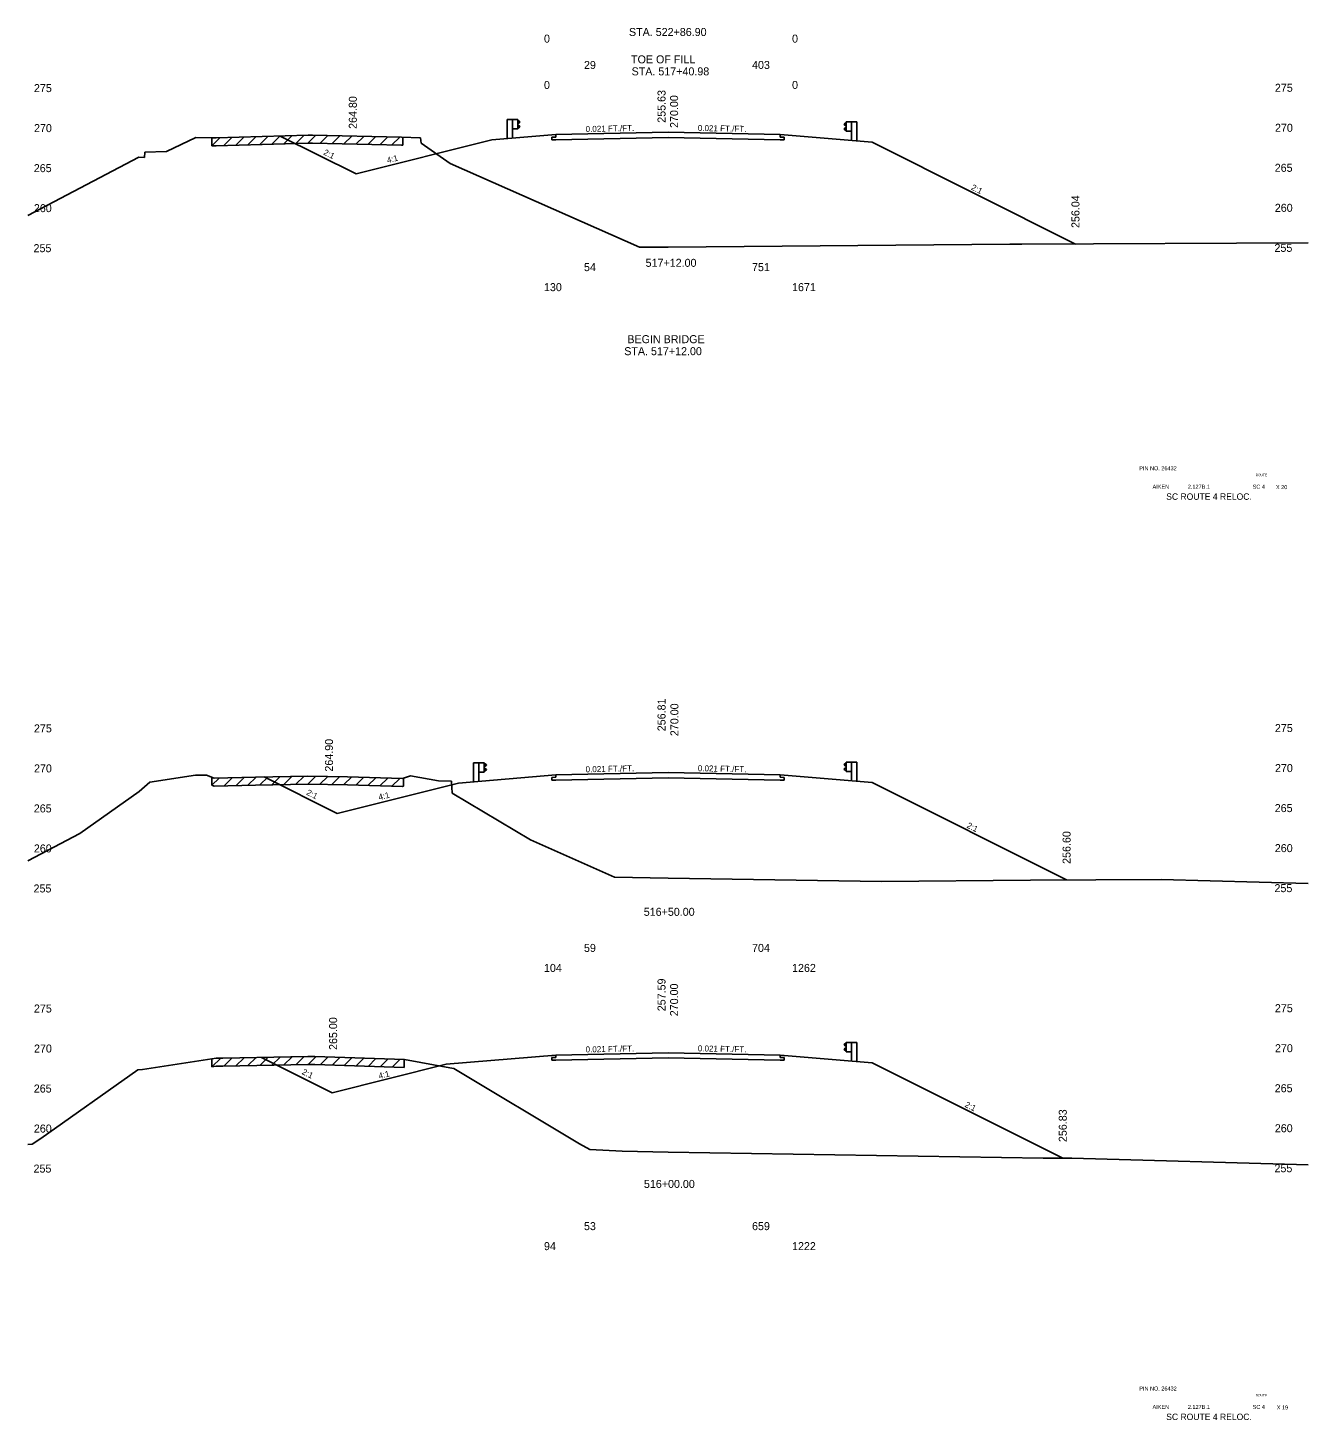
# Model space of a CAD drawing. Extents: x 2967 to 4323, y -3677 to -817.
# Drawn here: x 3188.8 to 3348.8, y -1510.8 to -1336.8 of the extents above; entities that cross this region are included whole.
import ezdxf

# ---------------------------------------------------------------- set-up
doc = ezdxf.new("R2010")
doc.units = 0
for name, color, linetype in [('Level 1', 7, 'Continuous'), ('Level 10', 7, 'Continuous'), ('Level 11', 7, 'Continuous'), ('Level 12', 7, 'Continuous'), ('Level 20', 7, 'Continuous'), ('Level 24', 7, 'Continuous'), ('Level 3', 7, 'Continuous'), ('Level 32', 7, 'Continuous'), ('Level 33', 7, 'Continuous'), ('Level 59', 7, 'Continuous'), ('Level 6', 7, 'Continuous'), ('Level 60', 7, 'Continuous'), ('Level 61', 7, 'Continuous'), ('Level 7', 7, 'Continuous')]:
    doc.layers.add(name, color=color, linetype=linetype)

msp = doc.modelspace()

# ---------------------------------------------------------------- linework, layer by layer
at = {"layer": 'Level 11'}
for p, q in [((3254.76, -1350.43), (3254.26, -1350.44)), ((3254.76, -1350.43), (3254.26, -1350.44)), ((3254.76, -1350.43), (3254.26, -1350.44)), ((3254.26, -1350.44), (3254.26, -1350.78)), ((3254.26, -1350.44), (3254.26, -1350.78)), ((3254.26, -1350.44), (3254.26, -1350.78)), ((3254.26, -1350.78), (3254.76, -1350.77)), ((3254.26, -1350.78), (3254.76, -1350.77)), ((3254.26, -1350.78), (3254.76, -1350.77)), ((3254.76, -1350.13), (3254.76, -1350.43)), ((3254.76, -1350.13), (3254.76, -1350.43)), ((3254.76, -1350.13), (3254.76, -1350.43)), ((3282.76, -1350.43), (3282.76, -1350.13)), ((3282.76, -1350.43), (3282.76, -1350.13)), ((3283.26, -1350.44), (3282.76, -1350.43)), ((3283.26, -1350.44), (3282.76, -1350.43)), ((3282.76, -1350.77), (3283.26, -1350.78)), ((3282.76, -1350.77), (3283.26, -1350.78)), ((3283.26, -1350.78), (3283.26, -1350.44)), ((3283.26, -1350.78), (3283.26, -1350.44)), ((3254.76, -1430.43), (3254.26, -1430.44)), ((3254.26, -1430.44), (3254.26, -1430.78)), ((3254.26, -1430.78), (3254.76, -1430.77)), ((3254.76, -1430.13), (3254.76, -1430.43)), ((3282.76, -1430.43), (3282.76, -1430.13)), ((3283.26, -1430.44), (3282.76, -1430.43)), ((3282.76, -1430.77), (3283.26, -1430.78)), ((3283.26, -1430.78), (3283.26, -1430.44)), ((3254.76, -1465.43), (3254.26, -1465.44)), ((3254.26, -1465.44), (3254.26, -1465.78)), ((3254.26, -1465.78), (3254.76, -1465.77)), ((3254.76, -1465.13), (3254.76, -1465.43)), ((3282.76, -1465.43), (3282.76, -1465.13)), ((3283.26, -1465.44), (3282.76, -1465.43)), ((3282.76, -1465.77), (3283.26, -1465.78)), ((3283.26, -1465.78), (3283.26, -1465.44))]:
    msp.add_line(p, q, dxfattribs=at)
at = {"layer": 'Level 12'}
for p, q in [((3254.76, -1350.13), (3268.76, -1349.84)), ((3268.76, -1349.84), (3282.76, -1350.13)), ((3268.76, -1349.84), (3282.76, -1350.13)), ((3268.76, -1349.84), (3282.76, -1350.13)), ((3291.03, -1348.62), (3290.76, -1348.82)), ((3290.76, -1348.82), (3290.76, -1348.87)), ((3290.76, -1348.87), (3291.03, -1349.07)), ((3290.76, -1349.39), (3291.03, -1349.19)), ((3290.76, -1349.44), (3290.76, -1349.39)), ((3291.03, -1349.64), (3290.76, -1349.44)), ((3291.03, -1349.72), (3291.03, -1348.55)), ((3291.03, -1348.55), (3291.7, -1348.55)), ((3291.03, -1349.72), (3291.7, -1349.72)), ((3291.7, -1348.55), (3291.7, -1350.88)), ((3291.7, -1348.55), (3292.36, -1348.55)), ((3292.36, -1348.55), (3292.36, -1350.93)), ((3268.76, -1350.48), (3254.76, -1350.77)), ((3282.76, -1350.77), (3268.76, -1350.48)), ((3282.76, -1350.77), (3268.76, -1350.48)), ((3282.76, -1350.77), (3268.76, -1350.48)), ((3282.76, -1350.13), (3290.76, -1350.8)), ((3282.76, -1350.43), (3282.76, -1350.13)), ((3283.26, -1350.44), (3282.76, -1350.43)), ((3282.76, -1350.77), (3283.26, -1350.78)), ((3283.26, -1350.78), (3283.26, -1350.44)), ((3290.76, -1350.8), (3294.26, -1351.09)), ((3294.26, -1351.09), (3319.68, -1363.8)), ((3245.12, -1428.61), (3244.46, -1428.61)), ((3244.46, -1428.61), (3244.46, -1430.99)), ((3245.79, -1428.61), (3245.12, -1428.61)), ((3245.12, -1428.61), (3245.12, -1430.94)), ((3245.79, -1429.77), (3245.12, -1429.77)), ((3245.79, -1429.77), (3245.79, -1428.61)), ((3245.79, -1428.68), (3246.06, -1428.88)), ((3246.06, -1428.93), (3245.79, -1429.13)), ((3246.06, -1429.45), (3245.79, -1429.25)), ((3245.79, -1429.7), (3246.06, -1429.5)), ((3246.06, -1428.88), (3246.06, -1428.93)), ((3246.06, -1429.5), (3246.06, -1429.45)), ((3268.76, -1430.48), (3254.76, -1430.77)), ((3282.76, -1430.77), (3268.76, -1430.48)), ((3268.76, -1465.48), (3254.76, -1465.77)), ((3282.76, -1465.77), (3268.76, -1465.48))]:
    msp.add_line(p, q, dxfattribs=at)
at = {"layer": 'Level 24'}
for p, q in [((3248.66, -1348.26), (3248.66, -1350.64)), ((3248.66, -1348.26), (3249.32, -1348.26)), ((3249.99, -1348.26), (3249.32, -1348.26)), ((3249.32, -1348.26), (3249.32, -1350.59)), ((3249.99, -1349.42), (3249.32, -1349.42)), ((3249.99, -1349.42), (3249.99, -1348.26)), ((3249.99, -1348.33), (3250.26, -1348.53)), ((3250.26, -1348.58), (3249.99, -1348.78)), ((3250.26, -1349.1), (3249.99, -1348.9)), ((3249.99, -1349.35), (3250.26, -1349.15)), ((3250.26, -1348.53), (3250.26, -1348.58)), ((3250.26, -1349.15), (3250.26, -1349.1)), ((3291.03, -1348.62), (3290.76, -1348.82)), ((3291.03, -1348.62), (3290.76, -1348.82)), ((3290.76, -1348.82), (3290.76, -1348.87)), ((3290.76, -1348.82), (3290.76, -1348.87)), ((3290.76, -1348.87), (3291.03, -1349.07)), ((3290.76, -1348.87), (3291.03, -1349.07)), ((3290.76, -1349.39), (3291.03, -1349.19)), ((3290.76, -1349.39), (3291.03, -1349.19)), ((3290.76, -1349.44), (3290.76, -1349.39)), ((3290.76, -1349.44), (3290.76, -1349.39)), ((3291.03, -1349.64), (3290.76, -1349.44)), ((3291.03, -1349.64), (3290.76, -1349.44)), ((3291.03, -1349.72), (3291.03, -1348.55)), ((3291.03, -1348.55), (3291.7, -1348.55)), ((3291.03, -1349.72), (3291.03, -1348.55)), ((3291.03, -1348.55), (3291.7, -1348.55)), ((3291.03, -1349.72), (3291.7, -1349.72)), ((3291.03, -1349.72), (3291.7, -1349.72)), ((3291.7, -1348.55), (3291.7, -1350.88)), ((3291.7, -1348.55), (3292.36, -1348.55)), ((3291.7, -1348.55), (3291.7, -1350.88)), ((3291.7, -1348.55), (3292.36, -1348.55)), ((3292.36, -1348.55), (3292.36, -1350.93)), ((3292.36, -1348.55), (3292.36, -1350.93)), ((3245.12, -1428.61), (3244.46, -1428.61)), ((3244.46, -1428.61), (3244.46, -1430.99)), ((3245.12, -1428.61), (3244.46, -1428.61)), ((3244.46, -1428.61), (3244.46, -1430.99)), ((3245.79, -1428.61), (3245.12, -1428.61)), ((3245.12, -1428.61), (3245.12, -1430.94)), ((3245.79, -1428.61), (3245.12, -1428.61)), ((3245.12, -1428.61), (3245.12, -1430.94)), ((3245.79, -1429.77), (3245.12, -1429.77)), ((3245.79, -1429.77), (3245.12, -1429.77)), ((3245.79, -1429.77), (3245.79, -1428.61)), ((3245.79, -1429.77), (3245.79, -1428.61)), ((3245.79, -1428.68), (3246.06, -1428.88)), ((3245.79, -1428.68), (3246.06, -1428.88)), ((3246.06, -1428.93), (3245.79, -1429.13)), ((3246.06, -1428.93), (3245.79, -1429.13)), ((3246.06, -1429.45), (3245.79, -1429.25)), ((3246.06, -1429.45), (3245.79, -1429.25)), ((3245.79, -1429.7), (3246.06, -1429.5)), ((3245.79, -1429.7), (3246.06, -1429.5)), ((3246.06, -1428.88), (3246.06, -1428.93)), ((3246.06, -1428.88), (3246.06, -1428.93)), ((3246.06, -1429.5), (3246.06, -1429.45)), ((3246.06, -1429.5), (3246.06, -1429.45)), ((3291.03, -1428.62), (3290.76, -1428.82)), ((3290.76, -1428.82), (3290.76, -1428.87)), ((3290.76, -1428.87), (3291.03, -1429.07)), ((3290.76, -1429.39), (3291.03, -1429.19)), ((3290.76, -1429.44), (3290.76, -1429.39)), ((3291.03, -1429.64), (3290.76, -1429.44)), ((3291.03, -1429.72), (3291.03, -1428.55)), ((3291.03, -1428.55), (3291.7, -1428.55)), ((3291.03, -1429.72), (3291.7, -1429.72)), ((3291.7, -1428.55), (3291.7, -1430.88)), ((3291.7, -1428.55), (3292.36, -1428.55)), ((3292.36, -1428.55), (3292.36, -1430.93)), ((3291.03, -1463.62), (3290.76, -1463.82)), ((3290.76, -1463.82), (3290.76, -1463.87)), ((3290.76, -1463.87), (3291.03, -1464.07)), ((3290.76, -1464.39), (3291.03, -1464.19)), ((3290.76, -1464.44), (3290.76, -1464.39)), ((3291.03, -1464.64), (3290.76, -1464.44)), ((3291.03, -1464.72), (3291.03, -1463.55)), ((3291.03, -1463.55), (3291.7, -1463.55)), ((3291.03, -1464.72), (3291.7, -1464.72)), ((3291.7, -1463.55), (3291.7, -1465.88)), ((3291.7, -1463.55), (3292.36, -1463.55)), ((3292.36, -1463.55), (3292.36, -1465.93))]:
    msp.add_line(p, q, dxfattribs=at)
at = {"layer": 'Level 59'}
for p, q in [((3254.76, -1350.13), (3268.76, -1349.84)), ((3254.76, -1350.13), (3268.76, -1349.84)), ((3268.76, -1349.84), (3282.76, -1350.13)), ((3268.76, -1349.84), (3282.76, -1350.13)), ((3254.76, -1430.13), (3268.76, -1429.84)), ((3268.76, -1429.84), (3282.76, -1430.13)), ((3254.76, -1465.13), (3268.76, -1464.84)), ((3268.76, -1464.84), (3282.76, -1465.13))]:
    msp.add_line(p, q, dxfattribs=at)
at = {"layer": 'Level 6'}
for p, q in [((3246.76, -1350.8), (3254.76, -1350.13)), ((3282.76, -1350.13), (3290.76, -1350.8)), ((3282.76, -1350.13), (3290.76, -1350.8)), ((3290.76, -1350.8), (3294.26, -1351.09)), ((3290.76, -1350.8), (3294.26, -1351.09)), ((3242.56, -1431.15), (3254.76, -1430.13)), ((3282.76, -1430.13), (3290.76, -1430.8)), ((3290.76, -1430.8), (3294.26, -1431.09)), ((3241.03, -1466.28), (3254.76, -1465.13)), ((3282.76, -1465.13), (3290.76, -1465.8)), ((3290.76, -1465.8), (3294.26, -1466.09))]:
    msp.add_line(p, q, dxfattribs=at)
at = {"layer": 'Level 60'}
for p, q in [((3206.1, -1352.23), (3209.77, -1350.51)), ((3209.77, -1350.51), (3211.71, -1350.55)), ((3211.71, -1350.55), (3212.28, -1350.53)), ((3212.28, -1350.53), (3223.78, -1350.21)), ((3223.78, -1350.21), (3224.33, -1350.22)), ((3224.33, -1350.22), (3235.45, -1350.44)), ((3235.45, -1350.44), (3237.81, -1350.53)), ((3237.81, -1350.53), (3237.93, -1351.2)), ((3237.93, -1351.2), (3241.52, -1353.73)), ((3188.76, -1360.23), (3202.64, -1352.97)), ((3202.64, -1352.97), (3203.34, -1352.99)), ((3203.34, -1352.99), (3203.38, -1352.31)), ((3203.38, -1352.31), (3206.1, -1352.23)), ((3241.52, -1353.73), (3265.19, -1364.18)), ((3268.76, -1364.21), (3311.49, -1363.82)), ((3311.49, -1363.82), (3312.96, -1363.84)), ((3312.96, -1363.84), (3348.76, -1363.65)), ((3265.19, -1364.18), (3268.76, -1364.21)), ((3202.69, -1432.21), (3204.01, -1431.02)), ((3204.01, -1431.02), (3209.7, -1430.18)), ((3209.7, -1430.18), (3211.07, -1430.16)), ((3211.07, -1430.16), (3212.05, -1430.55)), ((3212.05, -1430.55), (3217.2, -1430.41)), ((3217.2, -1430.41), (3223.76, -1430.27)), ((3223.76, -1430.27), (3228.71, -1430.36)), ((3228.71, -1430.36), (3235.6, -1430.59)), ((3235.6, -1430.59), (3236.58, -1430.25)), ((3236.58, -1430.25), (3240.08, -1430.88)), ((3240.08, -1430.88), (3241.7, -1430.9)), ((3241.7, -1430.9), (3241.79, -1432.4)), ((3195.26, -1437.47), (3202.69, -1432.21)), ((3241.79, -1432.4), (3251.56, -1438.26)), ((3188.76, -1440.85), (3195.26, -1437.47)), ((3251.56, -1438.26), (3262.09, -1442.93)), ((3262.09, -1442.93), (3268.76, -1443.03)), ((3268.76, -1443.03), (3295.42, -1443.44)), ((3295.42, -1443.44), (3314.05, -1443.27)), ((3314.05, -1443.27), (3330.38, -1443.19)), ((3330.38, -1443.19), (3348.76, -1443.72)), ((3203.07, -1466.92), (3212.29, -1465.54)), ((3212.29, -1465.54), (3213.13, -1465.53)), ((3213.13, -1465.53), (3223.75, -1465.31)), ((3223.75, -1465.31), (3224.61, -1465.33)), ((3224.61, -1465.33), (3235.81, -1465.7)), ((3235.81, -1465.7), (3241.5, -1466.72)), ((3190.4, -1475.55), (3202.5, -1466.99)), ((3202.5, -1466.99), (3203.07, -1466.92)), ((3241.5, -1466.72), (3242.01, -1466.81)), ((3242.01, -1466.81), (3257.69, -1476.22)), ((3188.76, -1476.3), (3189.29, -1476.25)), ((3189.29, -1476.25), (3190.4, -1475.55)), ((3257.69, -1476.22), (3259.01, -1476.92)), ((3259.01, -1476.92), (3263.03, -1477.16)), ((3263.03, -1477.16), (3268.76, -1477.25)), ((3268.76, -1477.25), (3315.63, -1478)), ((3315.63, -1478), (3319.24, -1478.01)), ((3319.24, -1478.01), (3348.76, -1478.87))]:
    msp.add_line(p, q, dxfattribs=at)
at = {"layer": 'Level 61'}
for p, q in [((3212.77, -1350.52), (3211.74, -1351.55)), ((3211.74, -1350.55), (3211.74, -1351.55)), ((3211.74, -1351.55), (3212.28, -1351.53)), ((3212.28, -1351.53), (3223.78, -1351.21)), ((3214.27, -1350.48), (3213.24, -1351.51)), ((3215.77, -1350.44), (3214.74, -1351.46)), ((3217.27, -1350.39), (3216.24, -1351.42)), ((3218.77, -1350.35), (3217.74, -1351.38)), ((3220.27, -1350.31), (3219.24, -1351.34)), ((3221.77, -1350.27), (3220.74, -1351.29)), ((3223.27, -1350.22), (3222.24, -1351.25)), ((3224.72, -1350.23), (3223.74, -1351.21)), ((3223.78, -1351.21), (3224.33, -1351.22)), ((3224.33, -1351.22), (3235.45, -1351.44)), ((3226.23, -1350.26), (3225.24, -1351.24)), ((3227.73, -1350.29), (3226.74, -1351.27)), ((3229.23, -1350.32), (3228.24, -1351.3)), ((3230.73, -1350.35), (3229.74, -1351.33)), ((3232.23, -1350.38), (3231.24, -1351.36)), ((3233.73, -1350.4), (3232.74, -1351.39)), ((3235.23, -1350.43), (3234.24, -1351.41)), ((3235.45, -1351.44), (3235.61, -1351.44)), ((3235.61, -1351.44), (3235.61, -1350.44)), ((3211.76, -1430.43), (3211.76, -1431.43)), ((3212.66, -1430.53), (3211.76, -1431.43)), ((3211.76, -1431.43), (3212.05, -1431.55)), ((3212.05, -1431.55), (3217.2, -1431.41)), ((3214.29, -1430.49), (3213.26, -1431.52)), ((3215.79, -1430.45), (3214.76, -1431.48)), ((3217.29, -1430.4), (3216.26, -1431.43)), ((3217.2, -1431.41), (3223.76, -1431.27)), ((3218.78, -1430.37), (3217.76, -1431.39)), ((3220.28, -1430.34), (3219.26, -1431.36)), ((3221.78, -1430.31), (3220.76, -1431.33)), ((3223.28, -1430.28), (3222.26, -1431.3)), ((3224.74, -1430.29), (3223.76, -1431.27)), ((3223.76, -1431.27), (3228.71, -1431.36)), ((3226.24, -1430.32), (3225.26, -1431.3)), ((3227.74, -1430.34), (3226.76, -1431.33)), ((3229.23, -1430.38), (3228.26, -1431.35)), ((3228.71, -1431.36), (3235.6, -1431.59)), ((3230.73, -1430.43), (3229.76, -1431.4)), ((3232.23, -1430.48), (3231.26, -1431.45)), ((3233.73, -1430.53), (3232.76, -1431.5)), ((3235.23, -1430.58), (3234.26, -1431.55)), ((3235.6, -1431.59), (3235.7, -1431.56)), ((3235.7, -1431.56), (3235.7, -1430.56)), ((3212.86, -1465.53), (3211.77, -1466.62)), ((3211.77, -1465.62), (3211.77, -1466.62)), ((3213.13, -1466.53), (3223.75, -1466.31)), ((3214.29, -1465.5), (3213.27, -1466.52)), ((3215.79, -1465.47), (3214.77, -1466.49)), ((3217.29, -1465.44), (3216.27, -1466.46)), ((3218.79, -1465.41), (3217.77, -1466.43)), ((3220.29, -1465.38), (3219.27, -1466.4)), ((3221.79, -1465.35), (3220.77, -1466.37)), ((3223.29, -1465.31), (3222.27, -1466.34)), ((3223.75, -1466.31), (3224.61, -1466.33)), ((3224.74, -1465.34), (3223.77, -1466.31)), ((3224.61, -1466.33), (3235.78, -1466.7)), ((3226.24, -1465.39), (3225.27, -1466.35)), ((3227.74, -1465.44), (3226.77, -1466.4)), ((3229.24, -1465.49), (3228.27, -1466.45)), ((3230.74, -1465.54), (3229.77, -1466.5)), ((3232.24, -1465.58), (3231.27, -1466.55)), ((3233.74, -1465.63), (3232.77, -1466.6)), ((3235.24, -1465.68), (3234.27, -1466.65)), ((3235.78, -1466.7), (3235.78, -1465.7)), ((3211.77, -1466.62), (3212.29, -1466.54)), ((3212.29, -1466.54), (3213.13, -1466.53))]:
    msp.add_line(p, q, dxfattribs=at)
at = {"layer": 'Level 7'}
for p, q in [((3220.29, -1350.31), (3229.77, -1355.05)), ((3246.76, -1350.8), (3229.77, -1355.05)), ((3294.26, -1351.09), (3319.68, -1363.8)), ((3294.26, -1351.09), (3319.68, -1363.8)), ((3218.3, -1430.38), (3227.41, -1434.94)), ((3242.56, -1431.15), (3227.41, -1434.94)), ((3294.26, -1431.09), (3318.57, -1443.25)), ((3217.96, -1465.43), (3226.78, -1469.84)), ((3241.03, -1466.28), (3226.78, -1469.84)), ((3294.26, -1466.09), (3318.09, -1478.01))]:
    msp.add_line(p, q, dxfattribs=at)

# ---------------------------------------------------------------- texts
at = {"layer": 'Level 1'}
for s, p in [('0', (3253.26, -1338.64)), ('0', (3284.26, -1338.64)), ('29', (3258.26, -1341.93)), ('403', (3279.26, -1341.93)), ('0', (3253.26, -1344.43)), ('0', (3284.26, -1344.43)), ('54', (3258.26, -1367.19)), ('751', (3279.26, -1367.19)), ('130', (3253.26, -1369.69)), ('1671', (3284.26, -1369.69)), ('BEGIN BRIDGE', (3263.68, -1376.19)), ('STA. 517+12.00', (3263.29, -1377.69)), ('59', (3258.26, -1452.25)), ('704', (3279.26, -1452.25)), ('104', (3253.26, -1454.75)), ('1262', (3284.26, -1454.75)), ('53', (3258.26, -1487.01)), ('659', (3279.26, -1487.01)), ('94', (3253.26, -1489.51)), ('1222', (3284.26, -1489.51))]:
    msp.add_text(s, height=1, dxfattribs=at).set_placement(p)
at = {"layer": 'Level 10'}
for s, p in [('STA. 522+86.90', (3263.88, -1337.81)), ('TOE OF FILL', (3264.14, -1341.23)), ('STA. 517+40.98', (3264.21, -1342.73)), ('517+12.00', (3265.96, -1366.65)), ('516+50.00', (3265.73, -1447.74)), ('516+00.00', (3265.75, -1481.74))]:
    msp.add_text(s, height=1, dxfattribs=at).set_placement(p)
for s, p in [('255.63', (3268.45, -1348.65)), ('256.81', (3268.45, -1424.68)), ('257.59', (3268.45, -1459.66))]:
    msp.add_text(s, height=1, rotation=90, dxfattribs=at).set_placement(p)
at = {"layer": 'Level 20'}
for s, height, p in [('PIN NO. 26432', 0.5, (3327.65, -1392.07)), ('ROUTE', 0.3, (3342.19, -1392.81)), ('AIKEN', 0.5, (3329.31, -1394.37)), ('SC ROUTE 4 RELOC.', 0.8, (3331.02, -1395.76)), (' 2.127B.1', 0.5, (3333.53, -1394.37)), ('SC 4', 0.5, (3341.82, -1394.37)), ('X 20', 0.5, (3344.73, -1394.43)), ('PIN NO. 26432', 0.5, (3327.65, -1507.05)), ('ROUTE', 0.3, (3342.19, -1507.79)), ('AIKEN', 0.5, (3329.31, -1509.35)), ('SC ROUTE 4 RELOC.', 0.8, (3331.02, -1510.74)), (' 2.127B.1', 0.5, (3333.53, -1509.35)), ('SC 4', 0.5, (3341.82, -1509.35)), ('X 19', 0.5, (3344.84, -1509.42))]:
    msp.add_text(s, height=height, dxfattribs=at).set_placement(p)
at = {"layer": 'Level 3'}
for s, p in [(' 275', (3189.15, -1344.82)), (' 275', (3344.23, -1344.78)), (' 270', (3189.16, -1349.82)), (' 270', (3344.24, -1349.78)), (' 265', (3189.13, -1354.82)), (' 265', (3344.21, -1354.78)), (' 260', (3189.14, -1359.82)), (' 260', (3344.22, -1359.78)), (' 255', (3189.1, -1364.82)), (' 255', (3344.18, -1364.78)), (' 275', (3189.15, -1424.82)), (' 275', (3344.23, -1424.78)), (' 270', (3189.16, -1429.82)), (' 270', (3344.24, -1429.78)), (' 265', (3189.13, -1434.82)), (' 265', (3344.21, -1434.78)), (' 260', (3189.14, -1439.82)), (' 260', (3344.22, -1439.78)), (' 255', (3189.1, -1444.82)), (' 255', (3344.18, -1444.78)), (' 275', (3189.15, -1459.82)), (' 275', (3344.23, -1459.78)), (' 270', (3189.16, -1464.82)), (' 270', (3344.24, -1464.78)), (' 265', (3189.13, -1469.82)), (' 265', (3344.21, -1469.78)), (' 260', (3189.14, -1474.82)), (' 260', (3344.22, -1474.78)), (' 255', (3189.1, -1479.82)), (' 255', (3344.18, -1479.78))]:
    msp.add_text(s, height=1, dxfattribs=at).set_placement(p)
at = {"layer": 'Level 32'}
for s, rotation, p in [('0.021 FT./FT.', 1.1916, (3258.47, -1349.81)), ('0.021 FT./FT.', 1.1916, (3258.47, -1349.81)), ('0.021 FT./FT.', 1.1916, (3258.47, -1349.81)), ('0.021 FT./FT.', 358.8084, (3272.48, -1349.67)), ('0.021 FT./FT.', 358.8084, (3272.48, -1349.67)), ('0.021 FT./FT.', 358.8084, (3272.48, -1349.67)), ('2:1', 333.435, (3225.62, -1352.59)), ('4:1', 14.0362, (3233.73, -1353.71)), ('2:1', 333.435, (3306.57, -1356.97)), ('2:1', 333.435, (3306.57, -1356.97)), ('2:1', 333.435, (3306.57, -1356.97)), ('0.021 FT./FT.', 1.1916, (3258.47, -1429.81)), ('0.021 FT./FT.', 358.8084, (3272.48, -1429.67)), ('2:1', 333.435, (3223.5, -1432.57)), ('4:1', 14.0362, (3232.68, -1433.3)), ('2:1', 333.435, (3306.02, -1436.69)), ('0.021 FT./FT.', 1.1916, (3258.47, -1464.81)), ('0.021 FT./FT.', 358.8084, (3272.48, -1464.67)), ('2:1', 333.435, (3222.94, -1467.48)), ('4:1', 14.0362, (3232.68, -1468.13)), ('2:1', 333.435, (3305.78, -1471.57))]:
    msp.add_text(s, height=0.75, rotation=rotation, dxfattribs=at).set_placement(p)
at = {"layer": 'Level 33'}
for s, p in [('264.80', (3229.87, -1349.42)), ('256.04', (3320.18, -1361.8)), ('256.04', (3320.18, -1361.8)), ('256.04', (3320.18, -1361.8)), ('264.90', (3226.89, -1429.72)), ('256.60', (3319.07, -1441.25)), ('265.00', (3227.41, -1464.5)), ('256.83', (3318.59, -1476.01))]:
    msp.add_text(s, height=1, rotation=90, dxfattribs=at).set_placement(p)
at = {"layer": 'Level 59'}
for p in [(3270.02, -1349.67), (3270.06, -1425.66), (3270.02, -1460.66)]:
    msp.add_text(' 270.00', height=1, rotation=90, dxfattribs=at).set_placement(p)

doc.saveas('drawing.dxf')
